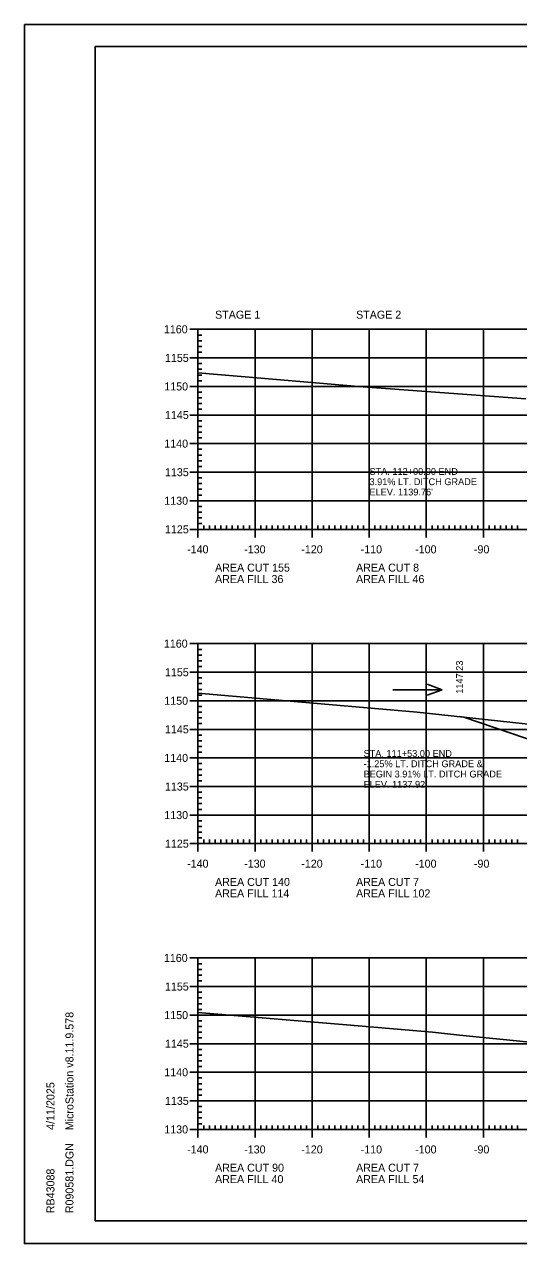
# Model space of a CAD drawing. Extents: x 1322838 to 1324533, y 339903 to 351025.
# Drawn here: x 1323533.3 to 1323619.9, y 340116.5 to 340329.8 of the extents above; entities that cross this region are included whole.
import ezdxf

# ---------------------------------------------------------------- set-up
doc = ezdxf.new("R2010")
doc.units = 0
for name, color, linetype in [('R_Axis', 7, 'Continuous'), ('R_Axis Annot', 7, 'Continuous'), ('R_Border', 7, 'Continuous'), ('R_Drive', 7, 'Continuous'), ('R_Exist Surface', 7, 'Continuous'), ('R_Fin Surface', 7, 'Continuous'), ('R_Fin Surface Annot', 7, 'Continuous'), ('R_Grid', 7, 'Continuous'), ('R_No Plot', 7, 'Continuous'), ('R_Water Annot', 7, 'Continuous')]:
    doc.layers.add(name, color=color, linetype=linetype)

msp = doc.modelspace()

# ---------------------------------------------------------------- linework, layer by layer
at = {"layer": 'R_Axis'}
for p, q in [((1323562.32, 340276.44), (1323565.12, 340276.44)), ((1323563.72, 340241.44), (1323563.72, 340276.44)), ((1323563.72, 340275.44), (1323564.42, 340275.44)), ((1323563.72, 340274.44), (1323564.42, 340274.44)), ((1323562.32, 340271.44), (1323565.12, 340271.44)), ((1323563.72, 340273.44), (1323564.42, 340273.44)), ((1323563.72, 340272.44), (1323564.42, 340272.44)), ((1323563.72, 340270.44), (1323564.42, 340270.44)), ((1323563.72, 340269.44), (1323564.42, 340269.44)), ((1323563.72, 340268.44), (1323564.42, 340268.44)), ((1323563.72, 340267.44), (1323564.42, 340267.44)), ((1323562.32, 340266.44), (1323565.12, 340266.44)), ((1323563.72, 340265.44), (1323564.42, 340265.44)), ((1323563.72, 340264.44), (1323564.42, 340264.44)), ((1323563.72, 340263.44), (1323564.42, 340263.44)), ((1323562.32, 340261.44), (1323565.12, 340261.44)), ((1323563.72, 340262.44), (1323564.42, 340262.44)), ((1323563.72, 340260.44), (1323564.42, 340260.44)), ((1323563.72, 340259.44), (1323564.42, 340259.44)), ((1323562.32, 340256.44), (1323565.12, 340256.44)), ((1323563.72, 340258.44), (1323564.42, 340258.44)), ((1323563.72, 340257.44), (1323564.42, 340257.44)), ((1323563.72, 340255.44), (1323564.42, 340255.44)), ((1323563.72, 340254.44), (1323564.42, 340254.44)), ((1323563.72, 340253.44), (1323564.42, 340253.44)), ((1323563.72, 340252.44), (1323564.42, 340252.44)), ((1323562.32, 340251.44), (1323565.12, 340251.44)), ((1323563.72, 340250.44), (1323564.42, 340250.44)), ((1323563.72, 340249.44), (1323564.42, 340249.44)), ((1323563.72, 340248.44), (1323564.42, 340248.44)), ((1323562.32, 340246.44), (1323565.12, 340246.44)), ((1323563.72, 340247.44), (1323564.42, 340247.44)), ((1323563.72, 340245.44), (1323564.42, 340245.44)), ((1323563.72, 340244.44), (1323564.42, 340244.44)), ((1323563.72, 340243.44), (1323564.42, 340243.44)), ((1323563.72, 340240.04), (1323563.72, 340242.84)), ((1323563.72, 340242.44), (1323564.42, 340242.44)), ((1323564.72, 340241.44), (1323564.72, 340242.14)), ((1323565.72, 340241.44), (1323565.72, 340242.14)), ((1323566.72, 340241.44), (1323566.72, 340242.14)), ((1323567.72, 340241.44), (1323567.72, 340242.14)), ((1323568.72, 340241.44), (1323568.72, 340242.14)), ((1323569.72, 340241.44), (1323569.72, 340242.14)), ((1323570.72, 340241.44), (1323570.72, 340242.14)), ((1323571.72, 340241.44), (1323571.72, 340242.14)), ((1323572.72, 340241.44), (1323572.72, 340242.14)), ((1323573.72, 340240.04), (1323573.72, 340242.84)), ((1323574.72, 340241.44), (1323574.72, 340242.14)), ((1323575.72, 340241.44), (1323575.72, 340242.14)), ((1323576.72, 340241.44), (1323576.72, 340242.14)), ((1323577.72, 340241.44), (1323577.72, 340242.14)), ((1323578.72, 340241.44), (1323578.72, 340242.14)), ((1323579.72, 340241.44), (1323579.72, 340242.14)), ((1323580.72, 340241.44), (1323580.72, 340242.14)), ((1323581.72, 340241.44), (1323581.72, 340242.14)), ((1323582.72, 340241.44), (1323582.72, 340242.14)), ((1323583.72, 340240.04), (1323583.72, 340242.84)), ((1323584.72, 340241.44), (1323584.72, 340242.14)), ((1323585.72, 340241.44), (1323585.72, 340242.14)), ((1323586.72, 340241.44), (1323586.72, 340242.14)), ((1323587.72, 340241.44), (1323587.72, 340242.14)), ((1323588.72, 340241.44), (1323588.72, 340242.14)), ((1323589.72, 340241.44), (1323589.72, 340242.14)), ((1323590.72, 340241.44), (1323590.72, 340242.14)), ((1323591.72, 340241.44), (1323591.72, 340242.14)), ((1323592.72, 340241.44), (1323592.72, 340242.14)), ((1323593.72, 340240.04), (1323593.72, 340242.84)), ((1323594.72, 340241.44), (1323594.72, 340242.14)), ((1323595.72, 340241.44), (1323595.72, 340242.14)), ((1323596.72, 340241.44), (1323596.72, 340242.14)), ((1323597.72, 340241.44), (1323597.72, 340242.14)), ((1323598.72, 340241.44), (1323598.72, 340242.14)), ((1323599.72, 340241.44), (1323599.72, 340242.14)), ((1323600.72, 340241.44), (1323600.72, 340242.14)), ((1323601.72, 340241.44), (1323601.72, 340242.14)), ((1323602.72, 340241.44), (1323602.72, 340242.14)), ((1323603.72, 340240.04), (1323603.72, 340242.84)), ((1323604.72, 340241.44), (1323604.72, 340242.14)), ((1323605.72, 340241.44), (1323605.72, 340242.14)), ((1323606.72, 340241.44), (1323606.72, 340242.14)), ((1323607.72, 340241.44), (1323607.72, 340242.14)), ((1323608.72, 340241.44), (1323608.72, 340242.14)), ((1323609.72, 340241.44), (1323609.72, 340242.14)), ((1323610.72, 340241.44), (1323610.72, 340242.14)), ((1323611.72, 340241.44), (1323611.72, 340242.14)), ((1323612.72, 340241.44), (1323612.72, 340242.14)), ((1323613.72, 340240.04), (1323613.72, 340242.84)), ((1323614.72, 340241.44), (1323614.72, 340242.14)), ((1323615.72, 340241.44), (1323615.72, 340242.14)), ((1323616.72, 340241.44), (1323616.72, 340242.14)), ((1323617.72, 340241.44), (1323617.72, 340242.14)), ((1323618.72, 340241.44), (1323618.72, 340242.14)), ((1323619.72, 340241.44), (1323619.72, 340242.14)), ((1323562.32, 340241.44), (1323565.12, 340241.44)), ((1323563.72, 340241.44), (1323843.72, 340241.44)), ((1323562.32, 340221.44), (1323565.12, 340221.44)), ((1323563.72, 340186.44), (1323563.72, 340221.44)), ((1323563.72, 340220.44), (1323564.42, 340220.44)), ((1323563.72, 340219.44), (1323564.42, 340219.44)), ((1323563.72, 340218.44), (1323564.42, 340218.44)), ((1323562.32, 340216.44), (1323565.12, 340216.44)), ((1323563.72, 340217.44), (1323564.42, 340217.44)), ((1323563.72, 340215.44), (1323564.42, 340215.44)), ((1323563.72, 340214.44), (1323564.42, 340214.44)), ((1323563.72, 340213.44), (1323564.42, 340213.44)), ((1323563.72, 340212.44), (1323564.42, 340212.44)), ((1323562.32, 340211.44), (1323565.12, 340211.44)), ((1323563.72, 340210.44), (1323564.42, 340210.44)), ((1323563.72, 340209.44), (1323564.42, 340209.44)), ((1323563.72, 340208.44), (1323564.42, 340208.44)), ((1323563.72, 340207.44), (1323564.42, 340207.44)), ((1323562.32, 340206.44), (1323565.12, 340206.44)), ((1323563.72, 340205.44), (1323564.42, 340205.44)), ((1323563.72, 340204.44), (1323564.42, 340204.44)), ((1323563.72, 340203.44), (1323564.42, 340203.44)), ((1323562.32, 340201.44), (1323565.12, 340201.44)), ((1323563.72, 340202.44), (1323564.42, 340202.44)), ((1323563.72, 340200.44), (1323564.42, 340200.44)), ((1323563.72, 340199.44), (1323564.42, 340199.44)), ((1323563.72, 340198.44), (1323564.42, 340198.44)), ((1323563.72, 340197.44), (1323564.42, 340197.44)), ((1323562.32, 340196.44), (1323565.12, 340196.44)), ((1323563.72, 340195.44), (1323564.42, 340195.44)), ((1323563.72, 340194.44), (1323564.42, 340194.44)), ((1323563.72, 340193.44), (1323564.42, 340193.44)), ((1323563.72, 340192.44), (1323564.42, 340192.44)), ((1323562.32, 340191.44), (1323565.12, 340191.44)), ((1323563.72, 340190.44), (1323564.42, 340190.44)), ((1323563.72, 340189.44), (1323564.42, 340189.44)), ((1323563.72, 340188.44), (1323564.42, 340188.44)), ((1323562.32, 340186.44), (1323565.12, 340186.44)), ((1323563.72, 340185.04), (1323563.72, 340187.84)), ((1323563.72, 340187.44), (1323564.42, 340187.44)), ((1323563.72, 340186.44), (1323843.72, 340186.44)), ((1323564.72, 340186.44), (1323564.72, 340187.14)), ((1323565.72, 340186.44), (1323565.72, 340187.14)), ((1323566.72, 340186.44), (1323566.72, 340187.14)), ((1323567.72, 340186.44), (1323567.72, 340187.14)), ((1323568.72, 340186.44), (1323568.72, 340187.14)), ((1323569.72, 340186.44), (1323569.72, 340187.14)), ((1323570.72, 340186.44), (1323570.72, 340187.14)), ((1323571.72, 340186.44), (1323571.72, 340187.14)), ((1323572.72, 340186.44), (1323572.72, 340187.14)), ((1323573.72, 340185.04), (1323573.72, 340187.84)), ((1323574.72, 340186.44), (1323574.72, 340187.14)), ((1323575.72, 340186.44), (1323575.72, 340187.14)), ((1323576.72, 340186.44), (1323576.72, 340187.14)), ((1323577.72, 340186.44), (1323577.72, 340187.14)), ((1323578.72, 340186.44), (1323578.72, 340187.14)), ((1323579.72, 340186.44), (1323579.72, 340187.14)), ((1323580.72, 340186.44), (1323580.72, 340187.14)), ((1323581.72, 340186.44), (1323581.72, 340187.14)), ((1323582.72, 340186.44), (1323582.72, 340187.14)), ((1323583.72, 340185.04), (1323583.72, 340187.84)), ((1323584.72, 340186.44), (1323584.72, 340187.14)), ((1323585.72, 340186.44), (1323585.72, 340187.14)), ((1323586.72, 340186.44), (1323586.72, 340187.14)), ((1323587.72, 340186.44), (1323587.72, 340187.14)), ((1323588.72, 340186.44), (1323588.72, 340187.14)), ((1323589.72, 340186.44), (1323589.72, 340187.14)), ((1323590.72, 340186.44), (1323590.72, 340187.14)), ((1323591.72, 340186.44), (1323591.72, 340187.14)), ((1323592.72, 340186.44), (1323592.72, 340187.14)), ((1323593.72, 340185.04), (1323593.72, 340187.84)), ((1323594.72, 340186.44), (1323594.72, 340187.14)), ((1323595.72, 340186.44), (1323595.72, 340187.14)), ((1323596.72, 340186.44), (1323596.72, 340187.14)), ((1323597.72, 340186.44), (1323597.72, 340187.14)), ((1323598.72, 340186.44), (1323598.72, 340187.14)), ((1323599.72, 340186.44), (1323599.72, 340187.14)), ((1323600.72, 340186.44), (1323600.72, 340187.14)), ((1323601.72, 340186.44), (1323601.72, 340187.14)), ((1323602.72, 340186.44), (1323602.72, 340187.14)), ((1323603.72, 340185.04), (1323603.72, 340187.84)), ((1323604.72, 340186.44), (1323604.72, 340187.14)), ((1323605.72, 340186.44), (1323605.72, 340187.14)), ((1323606.72, 340186.44), (1323606.72, 340187.14)), ((1323607.72, 340186.44), (1323607.72, 340187.14)), ((1323608.72, 340186.44), (1323608.72, 340187.14)), ((1323609.72, 340186.44), (1323609.72, 340187.14)), ((1323610.72, 340186.44), (1323610.72, 340187.14)), ((1323611.72, 340186.44), (1323611.72, 340187.14)), ((1323612.72, 340186.44), (1323612.72, 340187.14)), ((1323613.72, 340185.04), (1323613.72, 340187.84)), ((1323614.72, 340186.44), (1323614.72, 340187.14)), ((1323615.72, 340186.44), (1323615.72, 340187.14)), ((1323616.72, 340186.44), (1323616.72, 340187.14)), ((1323617.72, 340186.44), (1323617.72, 340187.14)), ((1323618.72, 340186.44), (1323618.72, 340187.14)), ((1323619.72, 340186.44), (1323619.72, 340187.14)), ((1323562.32, 340166.44), (1323565.12, 340166.44)), ((1323563.72, 340136.44), (1323563.72, 340166.44)), ((1323563.72, 340165.44), (1323564.42, 340165.44)), ((1323563.72, 340164.44), (1323564.42, 340164.44)), ((1323563.72, 340163.44), (1323564.42, 340163.44)), ((1323562.32, 340161.44), (1323565.12, 340161.44)), ((1323563.72, 340162.44), (1323564.42, 340162.44)), ((1323563.72, 340160.44), (1323564.42, 340160.44)), ((1323563.72, 340159.44), (1323564.42, 340159.44)), ((1323563.72, 340158.44), (1323564.42, 340158.44)), ((1323562.32, 340156.44), (1323565.12, 340156.44)), ((1323563.72, 340157.44), (1323564.42, 340157.44)), ((1323563.72, 340155.44), (1323564.42, 340155.44)), ((1323563.72, 340154.44), (1323564.42, 340154.44)), ((1323563.72, 340153.44), (1323564.42, 340153.44)), ((1323563.72, 340152.44), (1323564.42, 340152.44)), ((1323562.32, 340151.44), (1323565.12, 340151.44)), ((1323563.72, 340150.44), (1323564.42, 340150.44)), ((1323563.72, 340149.44), (1323564.42, 340149.44)), ((1323563.72, 340148.44), (1323564.42, 340148.44)), ((1323562.32, 340146.44), (1323565.12, 340146.44)), ((1323563.72, 340147.44), (1323564.42, 340147.44)), ((1323563.72, 340145.44), (1323564.42, 340145.44)), ((1323563.72, 340144.44), (1323564.42, 340144.44)), ((1323563.72, 340143.44), (1323564.42, 340143.44)), ((1323562.32, 340141.44), (1323565.12, 340141.44)), ((1323563.72, 340142.44), (1323564.42, 340142.44)), ((1323563.72, 340140.44), (1323564.42, 340140.44)), ((1323563.72, 340139.44), (1323564.42, 340139.44)), ((1323563.72, 340138.44), (1323564.42, 340138.44)), ((1323563.72, 340135.04), (1323563.72, 340137.84)), ((1323563.72, 340137.44), (1323564.42, 340137.44)), ((1323564.72, 340136.44), (1323564.72, 340137.14)), ((1323565.72, 340136.44), (1323565.72, 340137.14)), ((1323566.72, 340136.44), (1323566.72, 340137.14)), ((1323567.72, 340136.44), (1323567.72, 340137.14)), ((1323568.72, 340136.44), (1323568.72, 340137.14)), ((1323569.72, 340136.44), (1323569.72, 340137.14)), ((1323570.72, 340136.44), (1323570.72, 340137.14)), ((1323571.72, 340136.44), (1323571.72, 340137.14)), ((1323572.72, 340136.44), (1323572.72, 340137.14)), ((1323573.72, 340135.04), (1323573.72, 340137.84)), ((1323574.72, 340136.44), (1323574.72, 340137.14)), ((1323575.72, 340136.44), (1323575.72, 340137.14)), ((1323576.72, 340136.44), (1323576.72, 340137.14)), ((1323577.72, 340136.44), (1323577.72, 340137.14)), ((1323578.72, 340136.44), (1323578.72, 340137.14)), ((1323579.72, 340136.44), (1323579.72, 340137.14)), ((1323580.72, 340136.44), (1323580.72, 340137.14)), ((1323581.72, 340136.44), (1323581.72, 340137.14)), ((1323582.72, 340136.44), (1323582.72, 340137.14)), ((1323583.72, 340135.04), (1323583.72, 340137.84)), ((1323584.72, 340136.44), (1323584.72, 340137.14)), ((1323585.72, 340136.44), (1323585.72, 340137.14)), ((1323586.72, 340136.44), (1323586.72, 340137.14)), ((1323587.72, 340136.44), (1323587.72, 340137.14)), ((1323588.72, 340136.44), (1323588.72, 340137.14)), ((1323589.72, 340136.44), (1323589.72, 340137.14)), ((1323590.72, 340136.44), (1323590.72, 340137.14)), ((1323591.72, 340136.44), (1323591.72, 340137.14)), ((1323592.72, 340136.44), (1323592.72, 340137.14)), ((1323593.72, 340135.04), (1323593.72, 340137.84)), ((1323594.72, 340136.44), (1323594.72, 340137.14)), ((1323595.72, 340136.44), (1323595.72, 340137.14)), ((1323596.72, 340136.44), (1323596.72, 340137.14)), ((1323597.72, 340136.44), (1323597.72, 340137.14)), ((1323598.72, 340136.44), (1323598.72, 340137.14)), ((1323599.72, 340136.44), (1323599.72, 340137.14)), ((1323600.72, 340136.44), (1323600.72, 340137.14)), ((1323601.72, 340136.44), (1323601.72, 340137.14)), ((1323602.72, 340136.44), (1323602.72, 340137.14)), ((1323603.72, 340135.04), (1323603.72, 340137.84)), ((1323604.72, 340136.44), (1323604.72, 340137.14)), ((1323605.72, 340136.44), (1323605.72, 340137.14)), ((1323606.72, 340136.44), (1323606.72, 340137.14)), ((1323607.72, 340136.44), (1323607.72, 340137.14)), ((1323608.72, 340136.44), (1323608.72, 340137.14)), ((1323609.72, 340136.44), (1323609.72, 340137.14)), ((1323610.72, 340136.44), (1323610.72, 340137.14)), ((1323611.72, 340136.44), (1323611.72, 340137.14)), ((1323612.72, 340136.44), (1323612.72, 340137.14)), ((1323613.72, 340135.04), (1323613.72, 340137.84)), ((1323614.72, 340136.44), (1323614.72, 340137.14)), ((1323615.72, 340136.44), (1323615.72, 340137.14)), ((1323616.72, 340136.44), (1323616.72, 340137.14)), ((1323617.72, 340136.44), (1323617.72, 340137.14)), ((1323618.72, 340136.44), (1323618.72, 340137.14)), ((1323619.72, 340136.44), (1323619.72, 340137.14)), ((1323562.32, 340136.44), (1323565.12, 340136.44)), ((1323563.72, 340136.44), (1323843.72, 340136.44))]:
    msp.add_line(p, q, dxfattribs=at)
at = {"layer": 'R_Border'}
for p, q in [((1323545.72, 340325.9), (1323861.9, 340325.9)), ((1323545.72, 340120.44), (1323545.72, 340325.9)), ((1323545.72, 340120.44), (1323545.72, 340120.44)), ((1323861.9, 340120.44), (1323545.72, 340120.44))]:
    msp.add_line(p, q, dxfattribs=at)
at = {"layer": 'R_Exist Surface'}
for points in [[(1323563.72, 340268.82), (1323574.73, 340267.88), (1323591.84, 340266.44), (1323621.16, 340264.26)], [(1323563.72, 340212.78), (1323601.48, 340209.53), (1323602.14, 340209.47), (1323635.1, 340205.89)], [(1323563.72, 340156.91), (1323589.75, 340154.74), (1323604.81, 340153.44), (1323609.51, 340152.94), (1323621.84, 340151.7)]]:
    msp.add_lwpolyline(points, dxfattribs=at)
at = {"layer": 'R_Fin Surface'}
msp.add_lwpolyline([(1323609.54, 340208.67), (1323610.24, 340208.59), (1323610.27, 340208.59), (1323637.24, 340199.43)], dxfattribs=at)
at = {"layer": 'R_Grid'}
for p, q in [((1323563.72, 340276.44), (1323843.72, 340276.44)), ((1323563.72, 340241.44), (1323563.72, 340276.44)), ((1323573.72, 340241.44), (1323573.72, 340276.44)), ((1323583.72, 340241.44), (1323583.72, 340276.44)), ((1323593.72, 340241.44), (1323593.72, 340276.44)), ((1323603.72, 340241.44), (1323603.72, 340276.44)), ((1323613.72, 340241.44), (1323613.72, 340276.44)), ((1323563.72, 340271.44), (1323843.72, 340271.44)), ((1323563.72, 340266.44), (1323843.72, 340266.44)), ((1323563.72, 340261.44), (1323843.72, 340261.44)), ((1323563.72, 340256.44), (1323843.72, 340256.44)), ((1323563.72, 340251.44), (1323843.72, 340251.44)), ((1323563.72, 340246.44), (1323843.72, 340246.44)), ((1323563.72, 340241.44), (1323843.72, 340241.44)), ((1323563.72, 340221.44), (1323843.72, 340221.44)), ((1323563.72, 340186.44), (1323563.72, 340221.44)), ((1323573.72, 340186.44), (1323573.72, 340221.44)), ((1323583.72, 340186.44), (1323583.72, 340221.44)), ((1323593.72, 340186.44), (1323593.72, 340221.44)), ((1323603.72, 340186.44), (1323603.72, 340221.44)), ((1323613.72, 340186.44), (1323613.72, 340221.44)), ((1323563.72, 340216.44), (1323843.72, 340216.44)), ((1323563.72, 340211.44), (1323843.72, 340211.44)), ((1323563.72, 340206.44), (1323843.72, 340206.44)), ((1323563.72, 340201.44), (1323843.72, 340201.44)), ((1323563.72, 340196.44), (1323843.72, 340196.44)), ((1323563.72, 340191.44), (1323843.72, 340191.44)), ((1323563.72, 340186.44), (1323843.72, 340186.44)), ((1323563.72, 340166.44), (1323843.72, 340166.44)), ((1323563.72, 340136.44), (1323563.72, 340166.44)), ((1323573.72, 340136.44), (1323573.72, 340166.44)), ((1323583.72, 340136.44), (1323583.72, 340166.44)), ((1323593.72, 340136.44), (1323593.72, 340166.44)), ((1323603.72, 340136.44), (1323603.72, 340166.44)), ((1323613.72, 340136.44), (1323613.72, 340166.44)), ((1323563.72, 340161.44), (1323843.72, 340161.44)), ((1323563.72, 340156.44), (1323843.72, 340156.44)), ((1323563.72, 340151.44), (1323843.72, 340151.44)), ((1323563.72, 340146.44), (1323843.72, 340146.44)), ((1323563.72, 340141.44), (1323843.72, 340141.44)), ((1323563.72, 340136.44), (1323843.72, 340136.44))]:
    msp.add_line(p, q, dxfattribs=at)
at = {"layer": 'R_No Plot'}
for p, q in [((1323533.31, 340329.8), (1323866.65, 340329.8)), ((1323533.31, 340116.46), (1323866.65, 340116.46))]:
    msp.add_line(p, q, dxfattribs=at)
for points in [[(1323533.31, 340329.8), (1323866.65, 340329.8), (1323866.65, 340116.46), (1323533.31, 340116.46)], [(1323779.64, 340325.9), (1323799.26, 340325.9), (1323799.26, 340316.02), (1323815.37, 340316.02), (1323838.57, 340316.02), (1323838.57, 340283.35), (1323861.77, 340283.35), (1323861.9, 340120.44), (1323545.72, 340120.44), (1323545.72, 340325.9)], [(1323610.24, 340208.59), (1323635.1, 340205.89), (1323650.84, 340204.39), (1323656.46, 340203.79), (1323649.06, 340202.56), (1323644.22, 340201.75), (1323644.21, 340201.75), (1323641.31, 340200.79), (1323637.25, 340199.43), (1323637.24, 340199.43), (1323610.27, 340208.59)]]:
    msp.add_lwpolyline(points, close=True, dxfattribs=at)
at = {"layer": 'R_Water Annot'}
for p, q in [((1323606.52, 340213.38), (1323603.86, 340214.35)), ((1323597.83, 340213.38), (1323606.52, 340213.38)), ((1323606.52, 340213.38), (1323603.86, 340212.41))]:
    msp.add_line(p, q, dxfattribs=at)

# ---------------------------------------------------------------- texts
at = {"layer": 'R_Axis Annot'}
for s, p in [('STAGE 1', (1323566.72, 340278.3)), ('STAGE 2', (1323591.42, 340278.3)), ('1160', (1323557.75, 340275.74)), ('1155', (1323557.94, 340270.74)), ('1150', (1323557.82, 340265.74)), ('1145', (1323557.94, 340260.74)), ('1140', (1323557.82, 340255.74)), ('1135', (1323557.94, 340250.74)), ('1130', (1323557.82, 340245.74)), ('1125', (1323557.94, 340240.74)), ('-140', (1323561.82, 340237.24)), ('-130', (1323571.82, 340237.24)), ('-120', (1323581.82, 340237.24)), ('-110', (1323592.22, 340237.24)), ('-100', (1323601.77, 340237.24)), ('-90', (1323612.06, 340237.24)), ('AREA CUT 155', (1323566.72, 340234.04)), ('AREA CUT 8', (1323591.42, 340234.04)), ('AREA FILL 36', (1323566.72, 340232.04)), ('AREA FILL 46', (1323591.42, 340232.04)), ('1160', (1323557.75, 340220.74)), ('1155', (1323557.94, 340215.74)), ('1150', (1323557.82, 340210.74)), ('1145', (1323557.94, 340205.74)), ('1140', (1323557.82, 340200.74)), ('1135', (1323557.94, 340195.74)), ('1130', (1323557.82, 340190.74)), ('1125', (1323557.94, 340185.74)), ('-140', (1323561.82, 340182.24)), ('-130', (1323571.82, 340182.24)), ('-120', (1323581.82, 340182.24)), ('-110', (1323592.22, 340182.24)), ('-100', (1323601.77, 340182.24)), ('-90', (1323612.06, 340182.24)), ('AREA CUT 140', (1323566.72, 340179.04)), ('AREA CUT 7', (1323591.42, 340179.04)), ('AREA FILL 114', (1323566.72, 340177.04)), ('AREA FILL 102', (1323591.42, 340177.04)), ('1160', (1323557.75, 340165.74)), ('1155', (1323557.94, 340160.74)), ('1150', (1323557.82, 340155.74)), ('1145', (1323557.94, 340150.74)), ('1140', (1323557.82, 340145.74)), ('1135', (1323557.94, 340140.74)), ('1130', (1323557.82, 340135.74)), ('-140', (1323561.82, 340132.24)), ('-130', (1323571.82, 340132.24)), ('-120', (1323581.82, 340132.24)), ('-110', (1323592.22, 340132.24)), ('-100', (1323601.77, 340132.24)), ('-90', (1323612.06, 340132.24)), ('AREA CUT 90', (1323566.72, 340129.04)), ('AREA FILL 40', (1323566.72, 340127.04)), ('AREA CUT 7', (1323591.42, 340129.04)), ('AREA FILL 54', (1323591.42, 340127.04))]:
    msp.add_text(s, height=1.4, dxfattribs=at).set_placement(p)
at = {"layer": 'R_Border'}
for s, p in [('MicroStation v8.11.9.578', (1323541.91, 340136.3)), ('4/11/2025', (1323538.58, 340136.37)), ('R090581.DGN', (1323541.91, 340121.77)), ('RB43088', (1323538.58, 340121.77))]:
    msp.add_text(s, height=1.4, rotation=90, dxfattribs=at).set_placement(p)
at = {"layer": 'R_Drive'}
for s, p in [('STA. 112+00.00 END', (1323593.77, 340250.97)), ('3.91% LT. DITCH GRADE', (1323593.77, 340249.17)), ("ELEV. 1139.76'", (1323593.77, 340247.37)), ('STA. 111+53.00 END ', (1323592.73, 340201.62)), ('-1.25% LT. DITCH GRADE &', (1323592.73, 340199.82)), ('BEGIN 3.91% LT. DITCH GRADE', (1323592.73, 340198.02)), ("ELEV. 1137.92'", (1323592.73, 340196.22))]:
    msp.add_text(s, height=1.2, dxfattribs=at).set_placement(p)
at = {"layer": 'R_Fin Surface Annot'}
msp.add_text('1147.23', height=1.2, rotation=90, dxfattribs=at).set_placement((1323610.14, 340212.67))

doc.saveas('drawing.dxf')
